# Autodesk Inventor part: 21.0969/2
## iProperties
Created: 2012-01
Part Number: 21.0969/2
Document SubType Name: Modeling
Designer: Administrator
Density: 2.71 g/cm^3
Material: Aluminum-6061
Mass: 37.9255 g
Surface Area: 76.7695 cm^2
Volume: 13.9947 cm^3
Description: ANGLE 25 GD-Z
Stock Number: 21.0969/2 ANGLE 25 GD-Z
Author: Administrator
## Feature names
1. Base1
